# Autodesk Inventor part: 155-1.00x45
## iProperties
Created: 2007-06
Part Number: 155-1.00x45
Document SubType Name: Modeling
Designer: btaylor
Density: 1 g/cm^3
Author: btaylor
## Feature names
1. Sweep1
2. Extrusion1
3. Extrusion2
4. Fillet1
5. Fillet2
6. Extrusion3
7. Extrusion4
8. Sweep2
9. Fillet3
10. Fillet4
11. Chamfer1
12. Chamfer2
13. Fillet5
14. Fillet6
